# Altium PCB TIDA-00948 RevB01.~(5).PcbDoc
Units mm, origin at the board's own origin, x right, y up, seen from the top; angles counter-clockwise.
Board outline 125.73 x 87.63 mm, 2 copper layers (Top Layer, Bottom Layer), stack 1.575 mm thick; 30 components, 8 nets, 44 pads, 0 vias.
Unrouted connection lines stored in the file: 2.
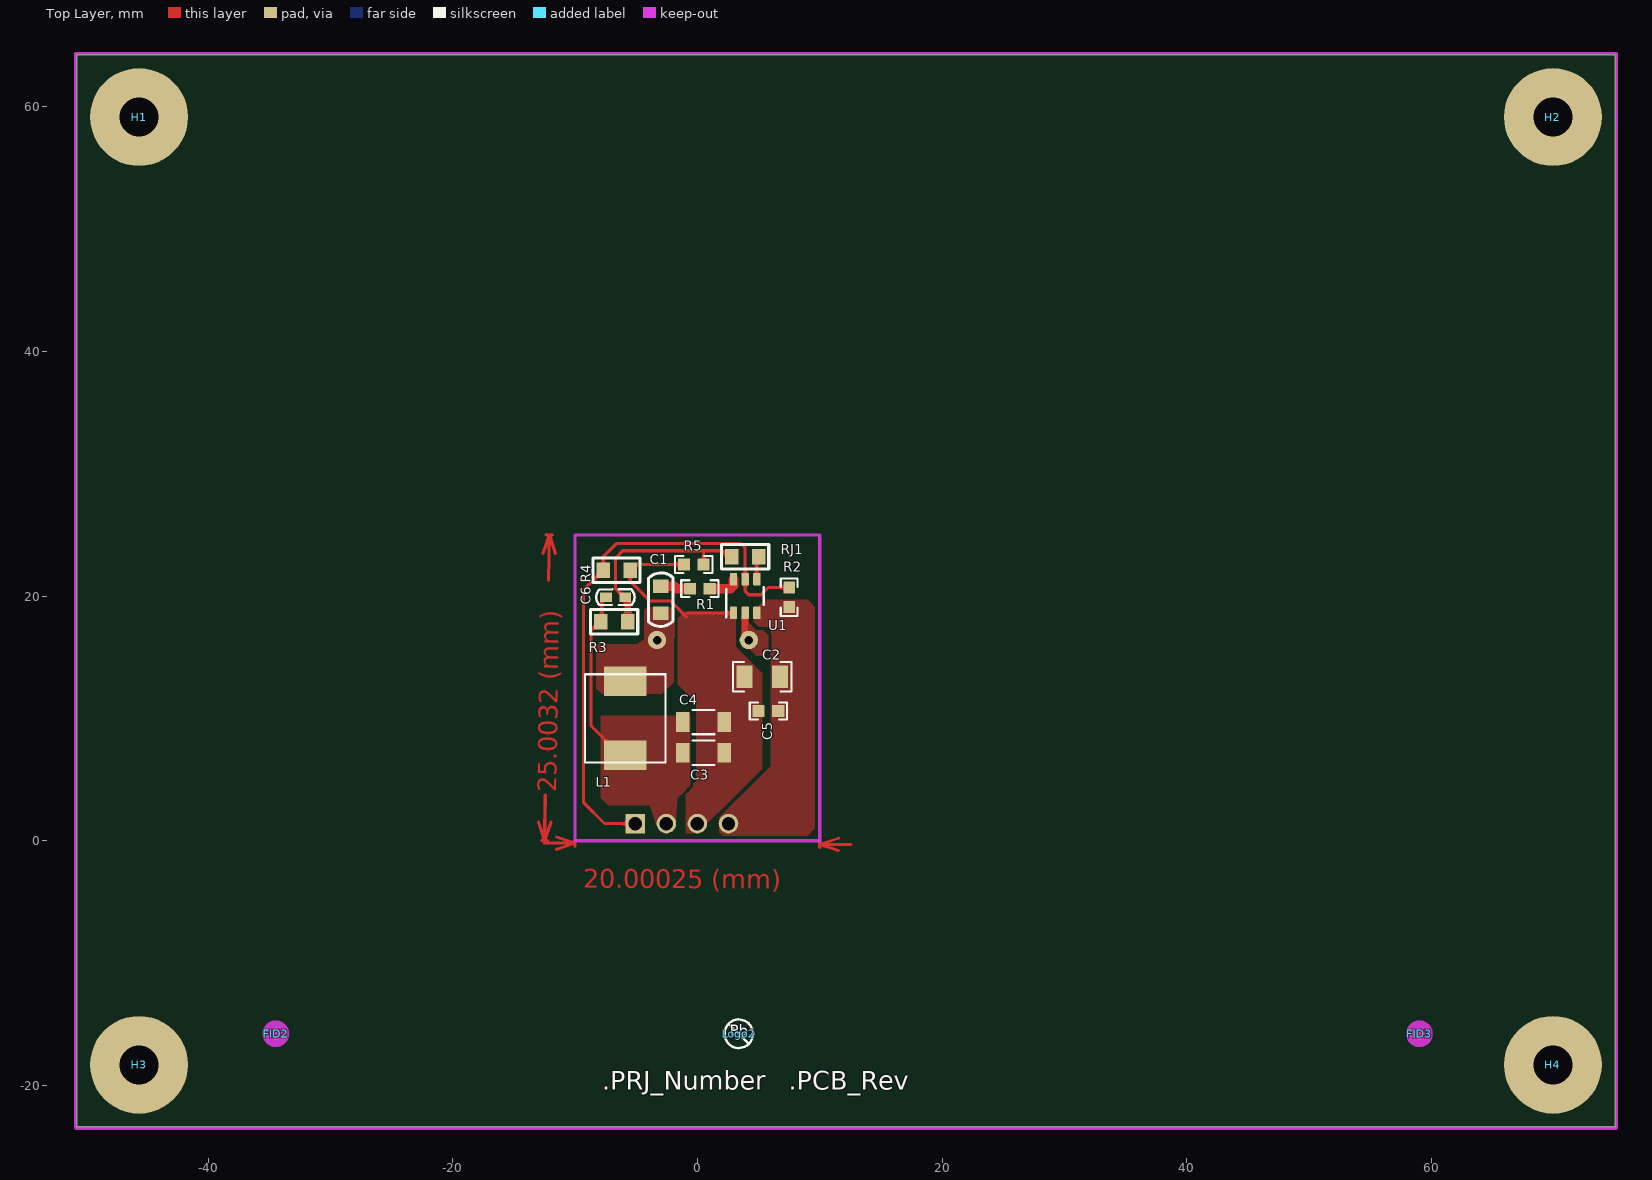
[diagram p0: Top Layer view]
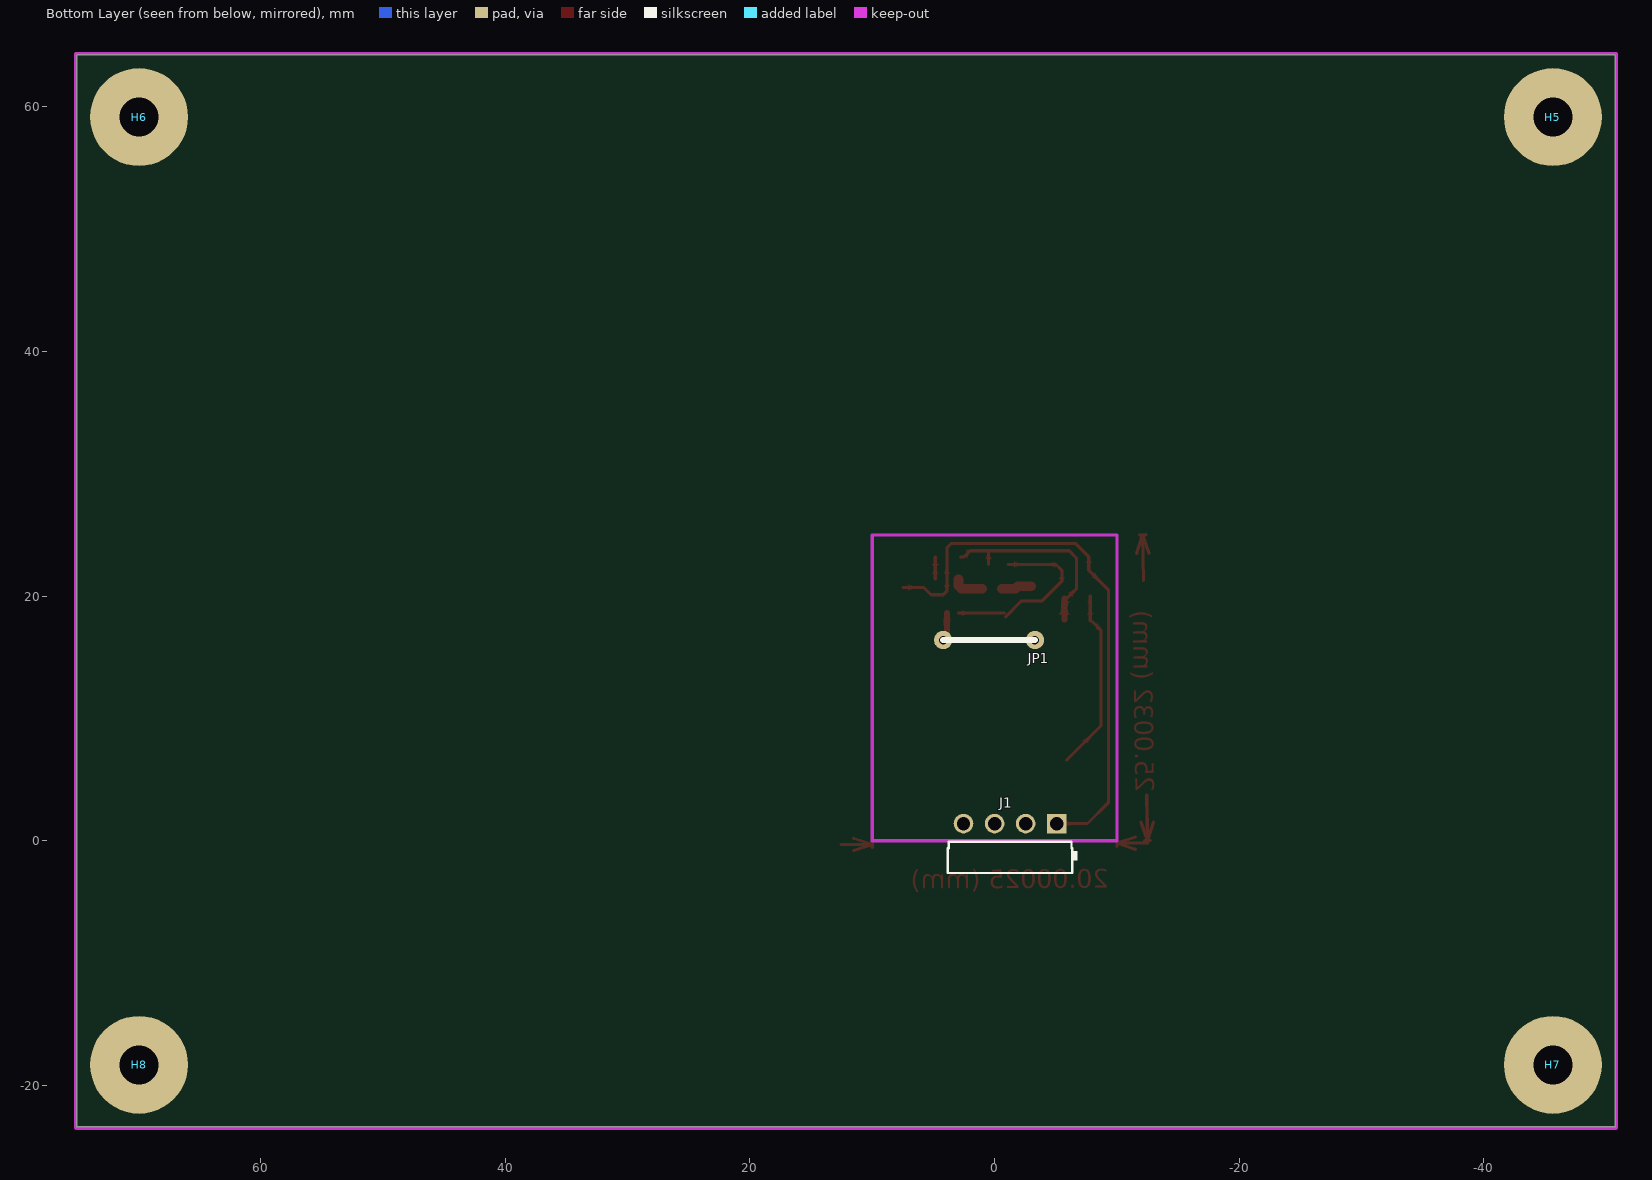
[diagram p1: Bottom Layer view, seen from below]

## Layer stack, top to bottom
Top Solder: solder mask 0.0102, Solder Resist, Dk 3.5
Top Layer: signal copper 0.0356
Dielectric1: core 1.5037, FR-4, Dk 4.8
Bottom Layer: signal copper 0.0356
Bottom Solder: solder mask 0.0102, Solder Resist, Dk 3.5

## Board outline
-50.72,-23.4 75.01,-23.4 75.01,64.23 -50.72,64.23

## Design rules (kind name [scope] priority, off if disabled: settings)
AcuteAngle [All] p1: minimum=4.50000000000000E+0001 checktracksonly=FALSE
AssemblyTestPointUsage [All] p1: valid=2
Clearance Clearance_Keepouts [((IsTrack Or IsArc) And Not InPoly) And IsFree and IsKeepOut vs ((IsTrack Or IsArc) And Not InPoly) And IsFree and IsKeepOut] p1 off: gap=0
Clearance Clearance_BoardEdge_MountingHoles [OnCopper and InComponentClass('Mounting Holes') vs IsKeepOut] p2 off: gap=1.016
Clearance Clearance_BoardEdge_Poly [OnCopper and InPoly vs IsKeepOut] p3 off: gap=0.635
Clearance Clearance_BoardEdge [OnCopper and Not InComponentClass('Logo') and not InComponentClass('FiducialMark') and not InRegion(1000,500,4000,800) and Not IsKeepout vs IsKeepOut] p4 off: gap=1.905
Clearance Clearance_Poly [InPolygon] p5 off: gap=0.635
Clearance [All] p6: gap=0.254
ComponentClearance ComponentClearance_MountingHoles_FiducialMarks [InComponentClass('Mounting Holes') vs InComponentClass('FiducialMark')] p1: gap=1.27 collisioncheckmode=3 verticalgap=0.254 showdistances=FALSE
ComponentClearance ComponentClearance_Shunt [InComponentClass('Header') vs InComponentClass('Shunt')] p2: gap=0 collisioncheckmode=3 verticalgap=0 showdistances=FALSE
ComponentClearance ComponentClearance_Logo [InComponentClass('Logo')] p3: gap=1.27 collisioncheckmode=3 verticalgap=0.254 showdistances=FALSE
ComponentClearance ComponentClearance_ScrewToNut [(HasFootprint('NY PMS 440 0025 PH')) vs (HasFootprint('Keystone_1902C'))] p4: gap=0.127 collisioncheckmode=3 verticalgap=0.254 showdistances=FALSE
ComponentClearance ComponentClearance_MountingHoles [InComponentClass('Mounting Holes')] p5: gap=6.35 collisioncheckmode=3 verticalgap=2540 showdistances=FALSE
ComponentClearance ComponentClearance_SmallPassives [HasFootprint('0201*') or HasFootprint('0402*') or HasFootprint('0508') or HasFootprint('0603*') or HasFootprint('0612') or HasFootprint('0805*') or HasFootprint('0815*') or HasFootprint('0830*') or HasFootprint('1206*') or HasFootprint('1210*') or HasFootprint('1808*') or HasFootprint('1812*') or HasFootprint('1825*') or HasFootprint('2010*') or HasFootprint('2220*') or HasFootprint('2225*') or HasFootprint('2512*') or HasFootprint('2728*') or HasFootprint('3518*') vs HasFootprint('0201*') or HasFootprint('0402*') or HasFootprint('0508') or HasFootprint('0603*') or HasFootprint('0612') or HasFootprint('0805*') or HasFootprint('0815*') or HasFootprint('0830*') or HasFootprint('1206*') or HasFootprint('1210*') or HasFootprint('1808*') or HasFootprint('1812*') or HasFootprint('1825*') or HasFootprint('2010*') or HasFootprint('2220*') or HasFootprint('2225*') or HasFootprint('2512*') or HasFootprint('2728*') or HasFootprint('3518*')] p6: gap=0.508 collisioncheckmode=3 verticalgap=0.254 showdistances=FALSE
ComponentClearance ComponentClearance_THtoSMT [IsThruComponent vs IsSMTComponent] p7: gap=2.54 collisioncheckmode=3 verticalgap=0.762 showdistances=FALSE
ComponentClearance ComponentClearance_THtoTH [IsThruComponent vs IsThruComponent] p8: gap=3 collisioncheckmode=3 verticalgap=0.762 showdistances=FALSE
ComponentClearance [All] p9: gap=1.016 collisioncheckmode=3 verticalgap=0.254 showdistances=FALSE
DiffPairsRouting [All] p1: maxlimit=2.54 minlimit=0.254 mostfreqgap=0.254 toplayer_minwidth=0.381 toplayer_maxwidth=0.381 toplayer_prefwidth=0.381 bottomlayer_minwidth=0.381 bottomlayer_maxwidth=0.381 bottomlayer_prefwidth=0.381 maxuncoupledlength=25.4
FabricationTestPointUsage TestPointUsage [All] p1: valid=2 allowmultiple=FALSE
FabricationTestpoint Testpoint [All] p1: side=3 testpointundercomponent=TRUE minsize=1.016 maxsize=2.54 preferedsize=1.524 minholesize=0 maxholesize=1.016 preferedholesize=0.813 testpointgrid=0.025 allowsidetop=TRUE allowsidebottom=TRUE usegrid=TRUE gridtolerance=0
FanoutControl Fanout_LCC [IsLCC] p1: bgadir=Out bgaviamode=Centered fanoutstyle=Auto fanoutdirection=Alternating viagrid=0.025 // Fanout_LCC (Default Rule)
FanoutControl Fanout_BGA [IsBGA] p2: bgadir=Out bgaviamode=Centered fanoutstyle=Auto fanoutdirection=Alternating viagrid=0.025 // Fanout_BGA (Default Rule)
FanoutControl Fanout_Default [All] p4: bgadir=Out bgaviamode=Centered fanoutstyle=Auto fanoutdirection=Alternating viagrid=0.025 // Fanout_Default (Default Rule)
FanoutControl Fanout_Small [(CompPinCount < 5)] p5: bgadir=Out bgaviamode=Centered fanoutstyle=Auto fanoutdirection=OutThenIn viagrid=0.025 // Fanout_Small (Default Rule)
HoleSize [All] p1: absolutevalues=TRUE maxlimit=6.375 minlimit=0.203 maxpercent=80.000 minpercent=20.000
MinimumAnnularRing MinimumAnnularRing_ThermalPadVias [IsVia and InAnyComponent] p1: minimumring=0.15
MinimumAnnularRing [All] p2: minimumring=0.229
MinimumSolderMaskSliver MinimumSolderMaskSliver_Logo [InComponentClass('Logo') vs InComponentClass('Logo')] p1: minsoldermaskwidth=0.018
MinimumSolderMaskSliver [All] p2: minsoldermaskwidth=0.1
PlaneConnect [All] p1: planeconnectstyle=Relief reliefexpansion=0.254 reliefentries=4 reliefconductorwidth=0.254 reliefairgap=0.254
PolygonConnect [All] p1: connectstyle=Direct reliefconductorwidth=0.254 reliefentries=4 polygonreliefangle="90 Angle" airgapwidth=0.254
RoutingVias ThermalPadVias [IsVia and InAnyComponent] p1: holewidth=0.2 width=0.5 viastyle="Through Hole" minholewidth=0.2 minwidth=0.5 maxholewidth=0.33 maxwidth=0.6
RoutingVias [All] p2: holewidth=0.406 width=0.864 viastyle="Through Hole" minholewidth=0.2 minwidth=0.66 maxholewidth=1.016 maxwidth=1.651
SilkToBoardRegionClearance [Not ((IsComment or IsDesignator) And (Hide <> 'False')) and not InRegion(1000,500,4000,800)] p1:
SilkToSilkClearance SilkToSilkClearance_Pb-FreeLogo [(HasFootprint('Pb-Free_Overlay_Medium') OR HasFootprint('Pb-Free_Overlay_Small')) vs (HasFootprint('Pb-Free_Overlay_Medium') OR HasFootprint('Pb-Free_Overlay_Small'))] p1: silktosilkclearance=0
SilkToSilkClearance [All] p2: silktosilkclearance=0.102
SilkToSolderMaskClearance SilkToComonentPadClearance [IsPad and InAnycomponent] p1: minsilkscreentomaskgap=0.127 clearancetoexposedcopper=TRUE
SilkToSolderMaskClearance "Silk to Solder Mask Opening" [All] p2: minsilkscreentomaskgap=0.102 clearancetoexposedcopper=FALSE
SolderMaskExpansion [All] p1: expansion=0.05
UnpouredPolygon [All] p1: allowunpoured=FALSE
Width [All] p1: maxlimit=2.54 minlimit=0.152 preferedwidth=0.254 checkconnectedcopper=TRUE
14 further rules are at their usual default settings.

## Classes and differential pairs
component class "Mounting Holes": H1 H2 H3 H4
component class TID_Hardware: FID2 FID3 H1 H2 H3 H4 H5 H6 H7 H8 Logo2 ZZ2 ZZ3 ZZ4
component class FiducialMark: FID2 FID3
component class AssemblyNote: ZZ2 ZZ3 ZZ4
component class Header: JP1
component class "TIDA-00948 RevA": C1 C2 C3 C4 C5 C6 JP1 L1 R1 R2 R3 R5 U1

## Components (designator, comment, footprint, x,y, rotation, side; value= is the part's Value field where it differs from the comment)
C1 "GRM188R71E104KA01D" C/0805/SMT1 -3,20.7 r270 top
C2 "GRM31CR71E106KA12L" 1206 5.3,13.4 r180 top
C3 "GCM31CR71A226KE02" 1206_190 0.5,7.2 r0 top
C4 "GCM31CR71A226KE02" 1206_190 0.5,9.7 r0 top
C5 "GRM188R71E104KA01D" 0603 5.8,10.6 r180 top
C6 "06033C101KAT2A" C/0603 -6.7,19.9 r0 top
FID2 "Fiducial" Fiducial10-20 -34.464,-15.78 r0 top
FID3 "Fiducial" Fiducial10-20 59.008,-15.78 r0 top
H1 "NY PMS 440 0025 PH" "NY PMS 440 0025 PH" -45.64,59.15 r0 top locked
H2 "NY PMS 440 0025 PH" "NY PMS 440 0025 PH" 69.93,59.15 r0 top locked
H3 "NY PMS 440 0025 PH" "NY PMS 440 0025 PH" -45.64,-18.32 r0 top locked
H4 "NY PMS 440 0025 PH" "NY PMS 440 0025 PH" 69.93,-18.32 r0 top locked
H5 "1902C" Keystone_1902C -45.64,59.15 r180 bottom locked
H6 "1902C" Keystone_1902C 69.93,59.15 r180 bottom locked
H7 "1902C" Keystone_1902C -45.64,-18.32 r180 bottom locked
H8 "1902C" Keystone_1902C 69.93,-18.32 r180 bottom locked
J1 "61300411021" Wurth_61300411021 -1.27,1.4 r0 bottom
JP1 "Comment" JUMP-7.5 -3.3,16.4 r0 bottom
L1 "LPS8045B-333MRB" WE-PD-M -5.9,10 r270 top
Logo2 "Pb-Free Symbol" Pb-Free_Overlay_Small 3.382,-15.78 r0 top
R1 "CRCW06030000Z0EA" 0603 0.2,20.6 r180 top
R2 "CRCW0603510KJNEA" 0603 7.5,19.9 r270 top
R3 "CRCW0603100KFKEA" R/0805/SMT1 -6.8,17.9 r180 top
R4 "CRCW0603100KFKEA" R/0805/SMT1 -6.6,22.1 r180 top (schematic designator R3)
R5 "CRCW060313K3FKEA" 0603 -0.298,22.577 r0 top
RJ1 "Comment" R/0805/SMT1 3.9,23.2 r0 top
U1 "TPS54202DDCR" DDC0006A_N 3.9,20 r90 top
ZZ2 "These assemblies are ESD sensitive, ESD precautions shall be observed." AssemblyNote -46.021,73.859 r0 top
ZZ3 "These assemblies must be clean and free from flux and all contaminants. Use of no clean flux is not acceptable." AssemblyNote -46.021,71.61 r0 top
ZZ4 "These assemblies must comply with workmanship standards IPC-A-610 Class 2, unless otherwise specified." AssemblyNote -46.021,69.361 r0 top

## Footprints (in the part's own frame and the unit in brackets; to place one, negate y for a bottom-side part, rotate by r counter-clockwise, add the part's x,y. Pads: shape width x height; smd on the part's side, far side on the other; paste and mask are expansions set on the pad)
0603 [mm] "0603 from SM-752 data"
  rect 1x0.95 smd: 1(-0.8,0) 2(0.8,0)
  silkscreen extent -1.52,-0.69 1.52,0.69, body extent -0.87,-0.47 0.87,0.47, height 1
1206 [mm] "1206 from SM-752 data"
  rect 1.3x1.85 smd: 1(-1.45,0) 2(1.45,0)
  silkscreen extent -2.4,-1.21 2.4,1.21, body extent -1.7,-0.9 1.7,0.9, height 1.35
1206_190 [mm] "1206_190"
  rect 1.1x1.6 smd: 1(-1.7,0) 2(1.7,0)
  silkscreen extent -0.9,-1 0.9,1, body extent -1.75,-0.95 1.75,0.95, height 1.9
AssemblyNote [mm] "Assembly Note"
C/0603 [mil]
  rect 38x30 smd: 1(-30.52,0.06) 2(31.48,0.06)
  silkscreen extent -62,-25 62,25
C/0805/SMT1 [mm]
  rect 1.1x1.25 smd: 1(-0.1,0) 2(2.1,0)
  silkscreen extent -1.19,-1 3.19,1.01
DDC0006A_N [mm]
  rrect17% 1x0.6 smd: 1(-1.375,0.95) 2(-1.375,0) 3(-1.375,-0.95) 4(1.375,-0.95) 5(1.375,0) 6(1.375,0.95)
  silkscreen extent -1.75,-1.52 0.7,1.53, body extent -1.43,-1.48 1.43,1.49, height 0.92
Fiducial10-20 [mm]
  round 1 smd mask+0.5: 1(0,0)
  Top Layer keep-out circle w1.178: c0,0 r0.5
JUMP-7.5 [mm]
  round 1.5 hole 0.7: 1(0,0) 2(7.5,0)
  silkscreen extent 0,0 7.5,0
Keystone_1902C [mm] "Hex Standoff, 4-40 threaded, nylon"
  body extent -3.68,-3.2 3.71,3.2, height 12.73
"NY PMS 440 0025 PH" [mm] "4-40 nylon screw and mounting hole"
  round 8 hole 3.2: 1(0,0)
  body extent -3.3,-3.3 3.3,3.3, height 2.69
Pb-Free_Overlay_Small [mm]
  silkscreen extent -1.16,-1.17 1.17,1.17
R/0805/SMT1 [mm]
  rect 1.1x1.25 smd: 1(-1.1,0) 2(1.1,0)
  silkscreen extent -1.92,-1 1.93,1
WE-PD-M [mm] "Wurth Elektronik recommended land pattern, 2008-01-04"
  rect 2.4x3.5 smd: 1(-3.035,0) 2(3.004,0)
  silkscreen extent -3.6,-3.3 3.6,3.3, body extent -3.81,-3.84 3.81,3.79, height 4.5
Wurth_61300411021 [mm] "Header, 2.54 mm, 4x1, R/A, TH"
  rect 1.6x1.6 hole 1.1: 1(-3.81,0)
  round 1.6 hole 1.1: 2(-1.27,0) 3(1.27,0) 4(3.81,0)
  silkscreen extent -5.5,1.5 5.08,4.04, body extent -5.08,-0.32 5.08,10.04, height 5.55

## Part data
C1 C5: "CAP, CERM, 0.1 μF, 25 V, +/- 10%, X7R, 0603"
C2: "CAP, CERM, 10 μF, 25 V, +/- 10%, X7R, 1206"
C3 C4: "CAP, CERM, 22 μF, 10 V, +/- 10%, X7R, AEC-Q200 Grade 1, 1206_190"
C6: "CAP, CERM, 100 pF, 25 V, +/- 10%, X7R, 0603"
FID2 FID3: "Fiducial mark.  There is nothing to buy or mount."
H1 H2 H3 H4: "Machine Screw, Round, #4-40 x 1/4, Nylon, Philips panhead"
H5 H6 H7 H8: "Standoff, Hex, 0.5\"L #4-40 Nylon"
J1: "Header, 2.54 mm, 4x1, Gold, R/A, TH"
L1: "Inductor, Shielded, Ferrite, 33 μH, 1.2 A, 0.121 ohm, SMD"
Logo2: library part Pb-Free
R1: "RES, 0, 5%, 0.1 W, 0603"
R2: "RES, 510 k, 5%, 0.1 W, 0603"
R3 R4: "RES, 100 k, 1%, 0.1 W, 0603"
R5: "RES, 13.3 k, 1%, 0.1 W, 0603"
U1: "4.5-V TO 28-V INPUT, 2-A OUTPUT, EMI FRIENDLY SYNCHRONUOUS STEP-DOWN CONVERTOR, DDC0006A"
ZZ2 ZZ3 ZZ4: library part AssemblyNote

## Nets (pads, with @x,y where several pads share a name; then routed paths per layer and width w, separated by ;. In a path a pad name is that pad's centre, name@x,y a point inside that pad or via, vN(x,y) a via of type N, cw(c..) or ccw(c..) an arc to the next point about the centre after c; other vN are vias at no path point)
+5V: C3.1 C4.1 C6.1 J1.2 L1.2 R3.2 | length 14.7
  Top Layer w0.254: R3.2@-8.022,17.878 -8.7,17.2 -8.7,9.4 L1.2@-5.9,6.6 ; R3.2@-7.822,17.978 C6.1@-7.822,20
EN: J1.1 R2.1 R4.2 U1.5 | length 45.4
  Top Layer w0.254: J1.1 -7.6,1.4 -9.3,3.1 -9.3,20.5 R4.2 -7.7,23.2 -6.6,24.3 3.519,24.3 3.9,23.919 U1.5 3.9,20.4 4.2,20.1 5.2,20.1 5.8,20.7 R2.1
GND: C2.2 C3.2 C4.2 C5.2 J1.3 R4.1 R5.1 U1.1 | length 15.1
  Top Layer w0.254: R5.1 -5.023,22.577 R4.1 -5.5,21.2 -3.9,19.6 -2.2,19.6 -0.9,18.3 ; -0.8,18.6 2.925,18.6 U1.1
NetC1_1: C1.1 R1.2 | length 2.5
  Top Layer w0.8: C1.1 -1.9,20.8 -1.7,20.6 R1.2
NetC1_2: C1.2 JP1.1 JP1.2 L1.1 U1.2 | length 1.5
  Top Layer w0.5: 3.9,17.1 U1.2
NetC6_2: C6.2 R3.1 R5.2 RJ1.1 RJ1.2 U1.4 | length 18.2
  Top Layer w0.254: C6.2@-5.9,19.801 -6.7,20.601 -6.7,23.1 -6.105,23.695 2.005,23.695 2.5,23.2 RJ1.1@2.778,23.2 ; R5.2 0.502,23.69 ; U1.4 RJ1.2@4.85,23.172
  Top Layer w0.5: R3.1@-5.7,18.1 C6.2@-5.7,19.8
NetR1_1: R1.1 U1.6 | length 2.6
  Top Layer w0.8: R1.1 2.7,20.6 2.946,20.846 U1.6@2.946,21.375
VIN: C2.1 C5.1 J1.4 R2.2 U1.3
pads on no net: FID2.1 FID3.1 H1.1 H2.1 H3.1 H4.1
copper on no net: | length 27.4
  Top Layer w0.254: -12.984,1.532 -12.5,0 ; -12.754,0.004 -12.246,-0.004 ; -12.632,23.484 -12.1,25 ; -12.54,-0.187 -10,-0.2 ; -12.441,3.715 -12.5,0 ; -12.354,25.004 -11.846,24.996 ; -12.159,21.285 -12.1,25 ; -11.968,1.516 -12.5,0 ; -11.616,23.468 -12.1,25 ; -11.527,-0.7 -10,-0.2 ; -11.521,0.316 -10,-0.2 ; -10.001,-0.454 -9.999,0.054 ; 9.999,-0.554 10.001,-0.046 ; 11.521,-0.816 10,-0.3 ; 11.527,0.2 10,-0.3 ; 12.54,-0.313 10,-0.3

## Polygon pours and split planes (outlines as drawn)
+5V on Top Layer "Top Layer-No Net 4" (solid, remove dead copper, pour order 10): -0.6,10.2 -0.6,4.5 -1.65,3.45 -1.779,1.547 -3.379,1.356 -3.893,2.9 -7.3,2.9 -7.9,3.5 -7.9,10.2
NetC1_2 on Top Layer "Top Layer-No Net 3" (solid, remove dead copper, pour order 8): 4.1,18.4 4.1,17.9 4.4,17.6 4.8,17.2 5.2,17.2 5.4,17.2 5.6,17 5.8,16.8 5.8,16.2 5.8,15.6 5.5,15.3 5.3,15.1 4.9,15.1 4.8,15.1 4.3,15.6 3.6,16.3 3.6,17.5 3.6,18.4
NetC1_2 on Top Layer "Top Layer-No Net 2" (solid, remove dead copper, pour order 7): -1.95,16.45 -1.95,12.95 -2.9,12 -7.8,12 -8.25,12.45 -8.25,15.85 -8.05,16.05 -5.65,16.05 -4.95,16.05 -4.35,16.45 -4.35,18.85 -4.1,19.1 -2.05,19.073 -2.05,18 -1.85,17.8 -1.85,15.85
GND on Top Layer "Top Layer-No Net" (solid, remove dead copper, pour order 6): 3.135,15.865 5.3,13.7 5.3,8.2 5.3,6.2 5.3,5.9 3.4,4 0,0.6 -0.951,0.6 -0.951,4.049 -0.4,4.6 -0.1,4.858 -0.1,11.3 -1.6,12.8 -1.6,18.2 -1.1,18.7 3.135,18.7
VIN on Top Layer "Top Layer-No Net 1" (solid, remove dead copper, pour order 9): 4.6,19 4.6,17.9 4.9,17.6 5,17.5 5.8,17.5 6,17.3 6,15.9 6,6.1 5.2,5.3 1.8,1.9 1.8,0.7 2.1,0.4 8.9,0.4 9,0.4 9.6,1 9.6,19.1 9.3,19.4 9,19.7 6.3,19.7 5.5,19.7 4.9,19.1

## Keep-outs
Keep-Out Layer:
  lines w0.254: -50.847,-23.4 ccw(c-50.72,-23.4) -50.72,-23.527 ; -50.847,-23.4 ccw(c-50.72,-23.4) -50.72,-23.527 ; -50.847,-23.4 -50.847,64.23 ; -50.847,64.23 cw(c-50.72,64.23) -50.72,64.357 ; -50.847,64.23 cw(c-50.72,64.23) -50.72,64.357 ; -50.72,-23.527 75.01,-23.527 ; -50.72,64.357 75.01,64.357 ; 75.01,-23.527 ccw(c75.01,-23.4) 75.137,-23.4 ; 75.01,-23.527 ccw(c75.01,-23.4) 75.137,-23.4 ; 75.01,64.357 cw(c75.01,64.23) 75.137,64.23 ; 75.01,64.357 cw(c75.01,64.23) 75.137,64.23 ; 75.137,-23.4 75.137,64.23 ; -10,0 10,0 10,25 -10,25 -10,0
  text ".Layer_Name" at -36.064,-45.206 h1.52

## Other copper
Top Layer:
  text "25.0032 (mm)" at -11.522,3.955 h1.52 r89.08
  text "20.00025 (mm)" at -9.312,-3.86 h1.52 r359.71
  text ".Layer_Name" at -36.064,-45.206 h1.52
Bottom Layer:
  text ".Layer_Name" at -36.064,-45.206 h1.52

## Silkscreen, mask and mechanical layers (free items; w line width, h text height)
Top Overlay:
  text ".PRJ_Number" at -7.794,-20.352 h1.52
  text ".PCB_Rev" at 7.446,-20.352 h1.52
  text ".Layer_Name" at -36.064,-45.206 h1.52
Bottom Overlay:
  text ".Layer_Name" at -36.064,-45.206 h1.52
Top Paste:
  text ".Layer_Name" at -36.064,-45.206 h1.52
Bottom Paste:
  text ".Layer_Name" at -36.064,-45.206 h1.52
Top Solder:
  lines w0.8: -7.3,3.6 -5.3,3.6 ; -6.4,4.8 -4.4,4.8 ; -4.1,3.6 -2.1,3.6 ; -3.15,4.75 -1.15,4.75 ; -0.9,15.6 -0.9,17.6 ; -0.7,12.5 -0.7,14.5 ; 0.2,16.1 0.2,18.1 ; 0.3,2.4 0.3,4.4 ; 0.6,13 0.6,15 ; 1.4,3.6 1.4,5.6 ; 1.5,16.2 1.5,18.2 ; 2.2,13.09 2.2,15.09 ; 2.6,3.8 2.6,5.8 ; 3.7,6 3.7,9.3 ; 4.2,1.2 4.2,3.2 ; 4.8,6.2 4.8,8.2 ; 5.4,1.2 5.4,4.4 ; 6.6,1.3 6.6,5.4 ; 6.7,6.7 6.7,8.7 ; 7.7,1.2 7.7,5.2 ; 7.8,7.3 7.8,9.3 ; 7.8,15.5 7.8,17.5 ; 8.9,1.2 8.9,3.9 ; 8.9,9.3 8.9,11.3 ; 9,5.5 9,7.5 ; 9,13 9,15 ; 9,16.7 9,18.7
  text ".Layer_Name" at -36.064,-45.206 h1.52
  text ".Layer_Name" at -36.064,-45.206 h1.52
Bottom Solder:
  text ".Layer_Name" at -36.064,-45.206 h1.52
Drill Guide:
  text ".Layer_Name" at -36.064,-45.206 h1.52
M1 Board Outline:
  the board outline again, w0.254
  text ".Layer_Name" at -36.064,-45.206 h1.52
M2 Board Dimensions:
  rectangle: -50.72,-30.385 -47.545,-27.21
  rectangle: -47.545,-33.56 -38.02,-30.385
  lines w0.178: -50.72,-30.385 -25.32,-30.385 ; -47.545,-33.56 -47.545,-27.21 ; -44.37,-33.56 -44.37,-27.21 ; -38.02,-33.56 -38.02,-27.21 ; -31.67,-33.56 -31.67,-27.21 ; -50.72,-33.56 -25.32,-33.56 -25.32,-27.21 -50.72,-27.21 -50.72,-33.56
  text ".Layer_Name" at -36.064,-45.206 h1.52
M3 3D STEP Top:
  text ".Layer_Name" at -36.064,-45.206 h1.52
M4 3D STEP Bottom:
  text ".Layer_Name" at -36.064,-45.206 h1.52
M5 Assembly Top:
  lines w0.254: -58.137,-47.026 109.503,-47.026 ; -58.137,-41.862 109.554,-41.862 ; -58.137,-36.697 -58.137,-52.191 43.59,-52.191 109.554,-52.191 109.554,-36.697 -58.124,-36.697 -58.124,-52.191 -18.106,-52.191 ; 4.474,-52.191 4.474,-36.697 ; 36.656,-41.862 36.656,-36.697 ; 57.992,-41.862 57.992,-36.697 ; 73.791,-52.356 73.791,-47.204
  text "COMPONENTS MARKED 'DNP' SHOULD NOT BE POPULATED." at -21.421,-31.49 h1.52
  text "ASSEMBLY VARIANT:" at -21.434,-34.424 h1.52
  text ".VariantName" at 4.881,-34.424 h1.52
  text "PCB VIEWED FROM TOP SIDE" at -56.524,-40.054 h1.52
  text "BOARD #:" at 6.379,-40.054 h1.52
  text ".PRJ_Number" at 20.235,-40.054 h1.52
  text "REV:" at 41.685,-40.054 h1.52
  text ".PCB_Rev" at 49.089,-40.054 h1.52
  text "SVN REV:" at 62.97,-40.054 h1.52
  text ".VersionControl_RevNumber" at 75.823,-40.054 h1.52
  text "TID #:" at 6.379,-45.219 h1.52
  text ".TID" at 20.235,-45.219 h1.52
  text "PLOT NAME =" at -56.524,-50.434 h1.52
  text ".plot_File_Name" at -36.064,-50.434 h1.52
  text "GENERATED    :" at 6.43,-50.434 h1.52
  text ".Print_Date" at 28.515,-50.434 h1.52
  text ".Print_Time" at 47.032,-50.434 h1.52
  text "TEXAS INSTRUMENTS" at 79.15,-50.434 h1.52
M6 Assembly Bottom:
  lines w0.254: -58.15,-41.874 109.541,-41.874 ; -58.099,-47.039 109.541,-47.039 ; -22.386,-52.369 -22.386,-47.217 ; -6.588,-41.874 -6.588,-36.71 ; 14.748,-41.874 14.748,-36.71 ; 46.93,-52.204 46.93,-36.71 ; 69.511,-52.204 109.529,-52.204 109.529,-36.71 -58.15,-36.71 -58.15,-52.204 7.814,-52.204 109.541,-52.204 109.541,-36.71
  text "COMPONENTS MARKED 'DNP' SHOULD NOT BE POPULATED." at 104.271,-31.477 h1.52
  text ".VariantName" at 77.753,-34.424 h1.52
  text "ASSEMBLY VARIANT:" at 104.144,-34.424 h1.52
  text ".VersionControl_RevNumber" at -24.418,-40.067 h1.52
  text "SVN REV:" at -11.566,-40.067 h1.52
  text ".PCB_Rev" at 2.315,-40.067 h1.52
  text "REV:" at 9.719,-40.067 h1.52
  text ".PRJ_Number" at 31.17,-40.067 h1.52
  text "BOARD #:" at 45.025,-40.067 h1.52
  text "PCB VIEWED FROM BOTTOM SIDE" at 107.928,-40.067 h1.52
  text ".TID" at 31.17,-45.231 h1.52
  text "TID #:" at 45.025,-45.231 h1.52
  text "TEXAS INSTRUMENTS" at -27.746,-50.447 h1.52
  text ".Print_Time" at 4.373,-50.447 h1.52
  text ".Print_Date" at 22.889,-50.447 h1.52
  text "GENERATED    :" at 44.974,-50.447 h1.52
  text ".plot_File_Name" at 87.469,-50.447 h1.52
  text "PLOT NAME =" at 107.928,-50.447 h1.52
M9 Title Sheet:
  drawing of 57 lines, arcs and shapes, not listed
  text "1" at -31.928,180.727 h1.78
  text "2" at 31.462,180.727 h1.78
  text "3" at 94.691,180.727 h1.78
  text "4" at 158.36,180.727 h1.78
  text "5" at 221.835,180.727 h1.78
  text "6" at 285.462,180.727 h1.78
  text "A" at -61.299,151.695 h1.78
  text "A" at 314.621,151.695 h1.78
  text "B" at -61.299,91.243 h1.78
  text "B" at 314.621,91.243 h1.78
  text "C" at -61.299,30.918 h1.78
  text "C" at 314.621,30.918 h1.78
  text "PROJECT TITLE:" at 237.405,-16.351 h1.14
  text ".PRJ_Title" at 238.675,-19.738 h1.78
  text "DESIGNED FOR:" at 237.405,-23.997 h1.14
  text ".PRJ_Customer" at 238.675,-27.553 h1.78
  text "D" at -61.299,-29.28 h1.78
  text "D" at 314.621,-29.28 h1.78
  text "FILE NAME:" at 237.405,-31.617 h1.14
  text ".PCB_File_Name_No_Path" at 238.675,-34.665 h1.78
  text "Texas Instruments (TI) and/or its licensors do not warrant the accuracy or completeness of this specification" at 111.18,-38.776 h1.14
  text "ENGINEER:" at 237.405,-38.983 h1.14
  text "LAYOUT BY:" at 275.632,-38.983 h1.14
  text "or any information contained therein. TI and/or its licensors do not warrant that this design will meet" at 110.037,-41.637 h1.14
  text ".PRJ_Engineer" at 238.675,-42.92 h1.78
  text ".PCB_Layout" at 276.915,-42.92 h1.78
  text "the specifications, will be suitable for your application or fit for any particular purpose, or will operate in" at 110.037,-44.499 h1.14
  text ".Layer_Name" at -36.064,-45.206 h1.52
  text "ALTIUM DESIGNER VERSION:" at 275.632,-46.857 h1.14
  text "an implementation. TI and/or its licensors do not warrant that the design is production worthy. You should" at 110.037,-47.361 h1.14
  text "completely validate and test your design implementation to confirm the system functionality for your application." at 111.18,-50.222 h1.14
  text ".print_Scale" at 238.675,-50.243 h1.78
  text ".Application_BuildNumber" at 276.915,-50.243 h1.78
  text "1" at -31.928,-55.493 h1.78
  text "2" at 31.462,-55.493 h1.78
  text "3" at 94.691,-55.493 h1.78
  text "4" at 158.36,-55.493 h1.78
  text "5" at 221.835,-55.493 h1.78
  text "6" at 285.462,-55.493 h1.78
M10 Fab Notes:
  drawing of 173 lines, arcs and shapes, not listed
  text "DESIGN INFORMATION" at 263.656,134.105 h1.52
  text "MIN. TRACK WIDTH:" at 247.284,129.533 h1.52
  text "8" at 275.129,129.533 h1.52
  text "MIL" at 279.06,129.533 h1.52
  text "MIN. CLEARANCE:" at 247.284,126.181 h1.52
  text "0.2" at 273.605,126.181 h1.52
  text "mm" at 279.06,126.181 h1.52
  text "MIN. VIA PAD SIZE:" at 247.284,122.828 h1.52
  text "24" at 274.367,122.828 h1.52
  text "MIL" at 279.06,122.828 h1.52
  text "0.05mm (2MIL)" at 264.937,119.228 h1.52
  text "MINIMUM ANNULAR RING" at 238.922,119.12 h1.52
  text "EXTERNAL" at 282.921,119.12 h1.52
  text "PER" at 244.002,116.122 h1.52
  text "IPC-D-275 CLASS 2 LEVEL C" at 249.59,116.122 h1.52
  text "MIL, HOLES" at 287.391,113.27 h1.52
  text "+/-" at 277.423,113.252 h1.52
  text "+/-" at 299.114,113.252 h1.52
  text "REGISTRATION TOLERANCES:" at 238.922,113.125 h1.52
  text "METAL" at 269.396,113.125 h1.52
  text "5" at 284.032,113.125 h1.52
  text "3" at 305.19,113.125 h1.52
  text "MIL" at 308.143,113.125 h1.52
  text "+/-" at 299.114,110.255 h1.52
  text "HOLE SIZE TOLERANCE (UNLESS OTHERWISE SPECIFIED):" at 238.922,110.128 h1.52
  text "3" at 305.19,110.128 h1.52
  text "MIL" at 308.143,110.128 h1.52
  text "MATERIAL:" at 237.023,104.808 h1.52
  text "FR-4 High Tg" at 262.079,101.243 h1.52
  text "FR-408" at 247.716,101.025 h1.52
  text "OTHER" at 285.511,101.025 h1.52
  text "X" at 258.144,100.933 h1.52
  text "62 MIL (1.6mm) +/-10%" at 255.847,96.892 h1.52
  text "THICKNESS:" at 238.922,96.784 h1.52
  text "X" at 252.591,96.784 h1.52
  text "OTHER" at 288.483,96.784 h1.52
  text "TOLERANCE:" at 238.922,92.77 h1.52
  text "X" at 260.24,92.77 h1.52
  text "ANSI IPC-6012 TYPE 3 CLASS 2" at 264.989,92.77 h1.52
  text "OTHER +/-" at 264.988,88.808 h1.52
  text "BOW & TWIST:" at 238.922,84.82 h1.52
  text "X" at 260.24,84.82 h1.52
  text "ANSI IPC-6012 TYPE 3 CLASS 2" at 264.989,84.82 h1.52
  text "OTHER +/-" at 264.988,80.794 h1.52
  text "DRILLING:" at 237.023,77.276 h1.52
  text "REFERENCE:" at 238.922,74.305 h1.52
  text "X" at 255.387,74.305 h1.52
  text "AS SHOWN" at 260.137,74.305 h1.52
  text "X" at 278.272,74.305 h1.52
  text "NC_DRILL FILES" at 281.752,74.305 h1.52
  text "PTH MIN COPPER THICKNESS:" at 238.922,70.291 h1.52
  text "X" at 273.218,70.291 h1.52
  text "1MIL" at 276.698,70.291 h1.52
  text "OTHER" at 289.321,70.291 h1.52
  text "BOARD FINISH:" at 237.023,66.253 h1.52
  text "SILKSCREEN:" at 240.965,63.256 h1.52
  text "X" at 265.064,63.256 h1.52
  text "TOP" at 268.265,63.256 h1.52
  text "X" at 278.018,63.256 h1.52
  text "BOTTOM" at 281.244,63.256 h1.52
  text "SILKSCREEN COLOR:" at 240.965,59.014 h1.52
  text "X" at 265.038,59.014 h1.52
  text "WHITE" at 268.265,59.014 h1.52
  text "OTHER" at 281.244,59.014 h1.52
  text "X" at 268.366,54.97 h1.52
  text "GREEN" at 271.592,54.97 h1.52
  text "OTHER" at 287.289,54.97 h1.52
  text "SOLDER RESIST COLOR:" at 240.965,54.696 h1.52
  text "X" at 268.366,50.652 h1.52
  text "MATTE" at 271.592,50.652 h1.52
  text "SEMI-GLOSS" at 287.278,50.636 h1.52
  text "IMMERSION GOLD (ENIG)" at 263.972,45.864 h1.52
  text "ENEPIG" at 297.946,45.78 h1.52
  text "SURFACE FINISH:" at 237.023,45.755 h1.52
  text "X" at 259.224,45.755 h1.52
  text "IMM. TIN/SILVER OR EQUIV" at 245.393,41.767 h1.52
  text "OTHER" at 281.752,41.767 h1.52
  text "ARRAY/PANEL:" at 237.023,37.221 h1.52
  text "CUT AND TRIM PER M1 BOARD OUTLINE" at 263.972,37.112 h1.52
  text "N.C. ROUTE" at 263.972,33.258 h1.52
  text "X" at 281.219,33.258 h1.52
  text "V. SCORE" at 285.969,33.258 h1.52
  text "CERTIFICATION:" at 237.023,29.778 h1.52
  text "MATERIALS AND WORKMANSHIP FOR ALL PCBS" at 255.438,29.778 h1.52
  text "TO MEET OR EXCEED THE REQUIREMENTS OF:" at 255.438,27.289 h1.52
  text "X" at 245.951,23.822 h1.52
  text "ANSI IPC-A-600F CLASS ->" at 249.482,23.822 h1.52
  text "X" at 291.114,23.822 h1.52
  text "2" at 294.135,23.822 h1.52
  text "1" at 286.134,23.784 h1.52
  text "3" at 303.126,23.784 h1.52
  text "X" at 266.628,19.771 h1.52
  text "RoHS" at 270.106,19.771 h1.52
  text "OTHER" at 286.474,19.771 h1.52
  text "PER ORDER" at 296.56,19.771 h1.52
  text "ALL BOARDS MUST MEET OR EXCEED UL94-V0 REQUIREMENTS." at 237.722,15.564 h1.52
  text "PCB MUST BEAR THE UL94V-0 UL REGISTERED MATERIAL ID NUMBER" at 237.722,12.516 h1.52
  text "ADDITIONAL REQUIREMENTS:" at 237.023,8.112 h1.52
  text "MICROSECTION:" at 238.922,5.191 h1.52
  text "YES" at 261.928,5.191 h1.52
  text "REQUIRED" at 283.81,1.225 h1.52
  text "BARE BOARD ELEC. TEST:" at 238.922,1.153 h1.52
  text "NONE" at 272.088,1.153 h1.52
  text "X" at 280.584,1.153 h1.52
  text "PER ORDER" at 298.846,1.153 h1.52
  text ".Layer_Name" at -36.064,-45.206 h1.52
M11 Gerber Information:
  lines w0.254: -58.137,-47.026 109.503,-47.026 ; -58.137,-41.862 109.554,-41.862 ; -58.137,-36.697 -58.137,-52.191 43.59,-52.191 109.554,-52.191 109.554,-36.697 -58.124,-36.697 -58.124,-52.191 -18.106,-52.191 ; 4.474,-52.191 4.474,-36.697 ; 36.656,-41.862 36.656,-36.697 ; 57.992,-41.862 57.992,-36.697 ; 73.791,-52.356 73.791,-47.204
  text "ALL ARTWORK VIEWED FROM TOP SIDE" at -56.524,-40.054 h1.52
  text "BOARD #:" at 6.379,-40.054 h1.52
  text ".PRJ_Number" at 20.235,-40.054 h1.52
  text "REV:" at 41.685,-40.054 h1.52
  text ".PCB_Rev" at 49.089,-40.054 h1.52
  text "SVN REV:" at 62.97,-40.054 h1.52
  text ".VersionControl_RevNumber" at 75.823,-40.054 h1.52
  text "LAYER NAME =" at -56.524,-45.206 h1.52
  text "TID #:" at 6.379,-45.219 h1.52
  text ".TID" at 20.235,-45.219 h1.52
  text "PLOT NAME =" at -56.524,-50.434 h1.52
  text ".plot_File_Name" at -36.064,-50.434 h1.52
  text "GENERATED    :" at 6.43,-50.434 h1.52
  text ".Print_Date" at 28.515,-50.434 h1.52
  text ".Print_Time" at 47.032,-50.434 h1.52
  text "TEXAS INSTRUMENTS" at 79.15,-50.434 h1.52
M12 Stackup:
  drawing of 191 lines, arcs and shapes, not listed
  text "Layer" at 197.961,175.482 h1.52
  text "Name" at 208.372,175.482 h1.52
  text "Material" at 231.988,175.482 h1.52
  text "Thickness" at 253.826,175.482 h1.52
  text "Constant" at 270.332,175.482 h1.52
  text "Board Layer Stack" at 284.806,175.482 h1.52
  text "1" at 197.961,172.434 h1.52
  text "Top Overlay" at 208.372,172.434 h1.52
  text "2" at 197.961,169.386 h1.52
  text "Top Solder" at 208.372,169.386 h1.52
  text "Solder Resist" at 231.988,169.386 h1.52
  text "0.40mil" at 253.826,169.386 h1.52
  text "3.5" at 270.332,169.386 h1.52
  text "3" at 197.961,166.338 h1.52
  text "Top Layer" at 208.372,166.338 h1.52
  text "Copper" at 231.988,166.338 h1.52
  text "1.40mil" at 253.826,166.338 h1.52
  text "4" at 197.961,163.29 h1.52
  text "Dielectric1" at 208.372,163.29 h1.52
  text "FR-4" at 231.988,163.29 h1.52
  text "59.20mil" at 253.826,163.29 h1.52
  text "4.8" at 270.332,163.29 h1.52
  text "5" at 197.961,160.242 h1.52
  text "Bottom Layer" at 208.372,160.242 h1.52
  text "Copper" at 231.988,160.242 h1.52
  text "1.40mil" at 253.826,160.242 h1.52
  text "6" at 197.961,157.194 h1.52
  text "Bottom Solder" at 208.372,157.194 h1.52
  text "Solder Resist" at 231.988,157.194 h1.52
  text "0.40mil" at 253.826,157.194 h1.52
  text "3.5" at 270.332,157.194 h1.52
  text "7" at 197.961,154.146 h1.52
  text "Bottom Overlay" at 208.372,154.146 h1.52
  text ".Layer_Name" at -36.064,-45.206 h1.52
M13 Component Bodies Top:
  text ".Layer_Name" at -36.064,-45.206 h1.52
M14 Component Bodies Bottom:
  text ".Layer_Name" at -36.064,-45.206 h1.52
M15 Courtyards Top:
  text ".Layer_Name" at -36.064,-45.206 h1.52
M16 Courtyards Bottom:
  text ".Layer_Name" at -36.064,-45.206 h1.52
Drill Drawing:
  circle w0.025: c90.827,54.622 r0.632
  lines w0.025: 90.195,50.197 91.459,50.197 91.459,51.461 90.195,51.461 90.195,50.197 ; 90.195,59.047 91.459,59.047 90.827,57.782 90.195,59.047
  lines w0.305: 88.472,49.059 142.27,49.059 ; 88.472,60.437 142.27,60.437 ; 97.879,45.266 97.879,64.23 ; 106.947,45.266 106.947,64.23 ; 123.751,45.266 123.751,64.23 ; 130.968,45.266 130.968,64.23 ; 88.472,45.266 142.27,45.266 142.27,64.23 88.472,64.23 88.472,45.266
  text "Symbol" at 90.748,61.575 h1.83
  text "Quantity" at 99.017,61.575 h1.83
  text "Finished Hole Size" at 108.085,61.575 h1.83
  text "Plated" at 124.889,61.575 h1.83
  text "Hole Type" at 132.106,61.575 h1.83
  text "2" at 99.017,57.782 h1.52
  text "27.56mil (0.700mm)" at 108.085,57.782 h1.52
  text "PTH" at 124.889,57.782 h1.52
  text "Round" at 132.106,57.782 h1.52
  text "4" at 99.017,53.99 h1.52
  text "43.31mil (1.100mm)" at 108.085,53.99 h1.52
  text "PTH" at 124.889,53.99 h1.52
  text "Round" at 132.106,53.99 h1.52
  text "4" at 99.017,50.197 h1.52
  text "125.98mil (3.200mm)" at 108.085,50.197 h1.52
  text "PTH" at 124.889,50.197 h1.52
  text "Round" at 132.106,50.197 h1.52
  text "10 Total" at 99.017,46.404 h1.52
  text ".Layer_Name" at -36.064,-45.206 h1.52

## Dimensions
-50.72,-33.56 to -25.32,-33.56 on M2 Board Dimensions
-50.72,-23.4 to -50.72,64.23 on M2 Board Dimensions
-50.72,-23.4 to 75.01,-23.4 on M2 Board Dimensions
